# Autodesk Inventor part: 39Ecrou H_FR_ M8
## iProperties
Created: 2011-01
Part Number: 39Ecrou H_FR_ M8
Document SubType Name: Modeling
Designer: eric
Density: 1 g/cm^3
Mass: 1.10039 g
Surface Area: 8.5432 cm^2
Volume: 1.10039 cm^3
Author: eric
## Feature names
1. Base1
